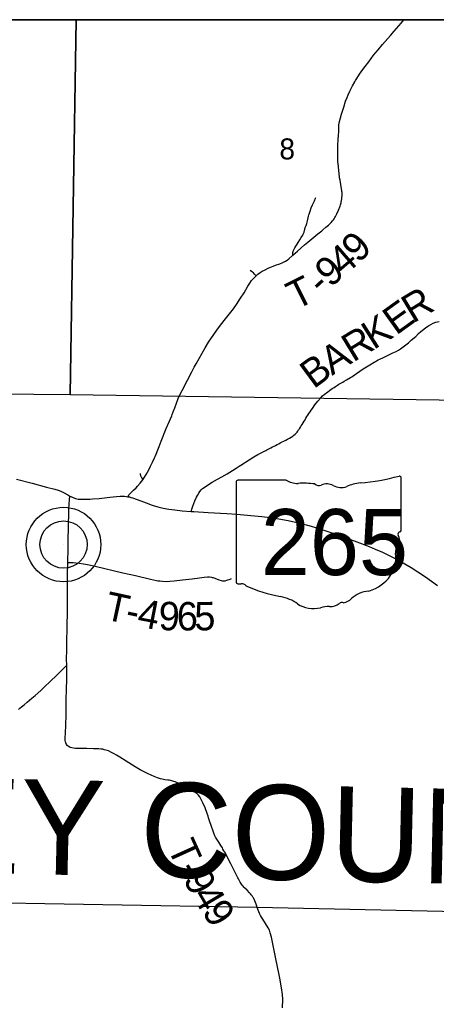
# Model space of a CAD drawing. Extents: x 0 to 34, y 0 to 22.
# Drawn here: x 5.085 to 5.917, y 18.929 to 20.9 of the extents above; entities that cross this region are included whole.
import ezdxf

# ---------------------------------------------------------------- set-up
doc = ezdxf.new("R2010")
doc.units = 0
for name, color, linetype in [('GM_X_Corporation', 7, 'Continuous'), ('GM_X_County_Text', 7, 'Continuous'), ('GM_X_Section_Text', 7, 'Continuous'), ('GM_X_State_Location', 7, 'Continuous'), ('GM_X_State_Route', 7, 'Continuous'), ('GM_X_State_Shield', 7, 'Continuous'), ('GM_X_Township_Road', 7, 'Continuous'), ('GM_X_Township_Road_Text', 7, 'Continuous'), ('GM_X_Township_Text', 7, 'Continuous'), ('GM_X_Unincorporated', 7, 'Continuous'), ('GM_X_Unincorporated_Location', 7, 'Continuous'), ('SH_Data', 7, 'Continuous')]:
    doc.layers.add(name, color=color, linetype=linetype)

msp = doc.modelspace()

# ---------------------------------------------------------------- linework, layer by layer
at = {"layer": 'GM_X_Corporation'}
for points in [[(5.1978, 20.9), (4.1826, 20.9), (4.1713, 20.1609), (5.1859, 20.1511)], [(6.2111, 20.9), (5.1978, 20.9), (5.1859, 20.1511), (6.1991, 20.1367)]]:
    msp.add_lwpolyline(points, close=True, dxfattribs=at)
at = {"layer": 'GM_X_State_Route'}
for points in [[(5.0782, 19.9821), (5.1096, 19.9743), (5.1384, 19.9666), (5.1547, 19.9622), (5.1618, 19.96), (5.1671, 19.958), (5.1722, 19.9555), (5.1809, 19.9507), (5.1851, 19.9485)], [(5.1851, 19.9485), (5.1869, 19.9475), (5.1914, 19.9456), (5.1966, 19.9438), (5.2019, 19.9426), (5.208, 19.942), (5.216, 19.942), (5.2184, 19.9421), (5.2252, 19.9424), (5.2302, 19.9427), (5.2437, 19.9439), (5.2647, 19.9461), (5.2783, 19.9478), (5.2858, 19.9484), (5.2908, 19.9485), (5.2945, 19.9482), (5.3011, 19.9472)], [(5.3011, 19.9472), (5.3039, 19.9467), (5.3068, 19.9459), (5.31, 19.9448), (5.327, 19.9387), (5.3375, 19.9348), (5.3492, 19.9306), (5.3605, 19.9272), (5.3714, 19.9245), (5.3825, 19.9224), (5.3948, 19.9208), (5.4097, 19.9193), (5.4271, 19.918), (5.4326, 19.9176), (5.4612, 19.9158), (5.499, 19.9137), (5.5182, 19.9124), (5.5683, 19.9078), (5.5855, 19.9057), (5.6027, 19.9031), (5.621, 19.8997), (5.6362, 19.8965), (5.647, 19.8939), (5.6626, 19.8897), (5.6804, 19.8843), (5.7005, 19.8778), (5.7204, 19.8709), (5.7583, 19.8571), (5.7833, 19.8476), (5.7954, 19.8427), (5.8095, 19.8363), (5.8245, 19.829), (5.8428, 19.8196), (5.8542, 19.8134), (5.8669, 19.8057), (5.8805, 19.797), (5.8954, 19.7869), (5.9197, 19.7697)]]:
    msp.add_lwpolyline(points, dxfattribs=at)
at = {"layer": 'GM_X_State_Shield'}
for p, q in [((5.847, 19.8804), (5.847, 19.9851)), ((5.5174, 19.9767), (5.5174, 19.7766)), ((5.6172, 19.9801), (5.5207, 19.9801)), ((5.847, 19.8804), (5.847, 19.8804))]:
    msp.add_line(p, q, dxfattribs=at)
for centre, major_axis, start_param, end_param in [((5.7296, 20.253), (0.3495, 0), 4.814394, 5.042369), ((5.8433, 19.9855), (0.00367, 0), 6.141152, 7.989035), ((5.5212, 19.9771), (0.00382, 0), 1.712693, 3.28349), ((5.6402, 20.0034), (0.037, 0), 4.042523, 4.731795), ((5.6524, 19.8678), (0.133, 0), 1.404758, 1.657858), ((5.6826, 19.9782), (0.0107, 0), 3.836095, 5.185415), ((5.6983, 19.955), (0.0222, 0), 0.950623, 2.079405), ((5.727, 19.9868), (0.0267, 0), 4.081561, 5.145723), ((5.7742, 19.919), (0.0703, 0), 1.699011, 2.107814), ((5.8462, 19.8727), (0.00568, 0), 1.883978, 3.671073), ((5.81, 19.8595), (0.0341, 0), 5.934695, 6.695948), ((5.8431, 19.88), (0.00393, 0), 5.05454, 6.418171), ((5.8601, 19.8366), (0.0248, 0), 2.387724, 3.262537), ((5.7492, 19.8233), (0.0874, 0), 5.101752, 6.440018), ((5.5212, 19.7761), (0.00385, 0), 3.00124, 4.508301), ((5.5218, 19.7966), (0.0294, 0), 4.665946, 4.897461), ((5.5278, 19.765), (0.0106, 0), 0.519207, 1.627899), ((5.6616, 19.9448), (0.2524, 0), 4.195997, 4.488961), ((5.5864, 19.6867), (0.079, 0), 0.823519, 1.323587), ((5.786, 19.7204), (0.0479, 0), 1.647645, 2.488434), ((5.6718, 19.764), (0.0501, 0), 4.026481, 4.996735), ((5.7008, 19.6948), (0.0412, 0), 1.495662, 1.94098), ((5.7044, 19.749), (0.0267, 0), 4.691044, 5.507374), ((5.7286, 19.7297), (0.00752, 0), 1.147584, 2.315152), ((5.7254, 19.7572), (0.0282, 0), 4.937069, 5.64225)]:
    msp.add_ellipse(centre, major_axis=major_axis, ratio=0.8, start_param=start_param, end_param=end_param, dxfattribs=at)
at = {"layer": 'GM_X_Township_Road'}
for points in [[(5.6308, 20.4295), (5.6352, 20.4335), (5.6399, 20.4376), (5.6541, 20.4505), (5.6603, 20.4557), (5.6806, 20.472), (5.6882, 20.4783), (5.6906, 20.4803), (5.6967, 20.4854), (5.7019, 20.4899), (5.7073, 20.495), (5.7101, 20.4983), (5.7117, 20.5004), (5.713, 20.5023), (5.7144, 20.5046), (5.7158, 20.5071), (5.7182, 20.5122), (5.7215, 20.5195), (5.725, 20.5275), (5.7258, 20.53), (5.7265, 20.5322), (5.727, 20.5339), (5.7274, 20.5358), (5.7279, 20.5386), (5.7284, 20.5419), (5.7287, 20.5449), (5.7289, 20.5481), (5.7289, 20.5527), (5.7289, 20.5551), (5.7288, 20.557), (5.7286, 20.5586), (5.728, 20.5623), (5.7263, 20.5711), (5.7249, 20.5795), (5.7241, 20.5842), (5.723, 20.594), (5.7227, 20.5972), (5.7215, 20.6077), (5.7207, 20.617), (5.7202, 20.6263), (5.7202, 20.6449), (5.7204, 20.6517), (5.721, 20.6581), (5.7214, 20.6622), (5.7218, 20.6678), (5.7223, 20.6771), (5.7224, 20.6845), (5.7228, 20.6901), (5.7232, 20.6932), (5.724, 20.6968), (5.7259, 20.704), (5.7279, 20.7112), (5.7322, 20.7255), (5.7361, 20.7372), (5.7389, 20.7448), (5.741, 20.75), (5.7443, 20.7573), (5.7497, 20.7678), (5.7543, 20.7759), (5.7559, 20.7786), (5.7585, 20.7828), (5.7639, 20.7911), (5.7707, 20.8007), (5.7751, 20.8067), (5.7821, 20.8161), (5.7919, 20.8289), (5.8008, 20.8401), (5.8095, 20.8506), (5.8149, 20.8566), (5.8259, 20.8683), (5.8332, 20.8768), (5.8467, 20.893), (5.8523, 20.9)], [(5.6308, 20.4295), (5.6305, 20.4313), (5.6304, 20.4322), (5.6304, 20.4329), (5.6304, 20.4337), (5.6305, 20.4346), (5.6306, 20.4355), (5.6309, 20.4364), (5.6312, 20.4373), (5.6315, 20.438), (5.6327, 20.4405), (5.6347, 20.4441), (5.6368, 20.4477), (5.6394, 20.4519), (5.6413, 20.455), (5.6445, 20.4604), (5.6469, 20.4647), (5.6503, 20.4699), (5.6512, 20.4715), (5.6521, 20.4731), (5.6525, 20.4742), (5.6529, 20.4754), (5.6533, 20.4769), (5.6537, 20.4784), (5.6544, 20.4815), (5.6548, 20.4829), (5.6554, 20.4846), (5.656, 20.486), (5.6573, 20.4888), (5.6582, 20.4908), (5.6588, 20.4928), (5.6601, 20.4982), (5.6612, 20.5043), (5.6619, 20.5078), (5.6625, 20.5102), (5.663, 20.5116), (5.6649, 20.5179), (5.6672, 20.5243), (5.6696, 20.53), (5.6737, 20.5383), (5.6759, 20.5437), (5.6763, 20.5447)], [(5.5573, 20.3885), (5.5609, 20.3916), (5.5653, 20.395), (5.5696, 20.3976), (5.574, 20.3998), (5.5829, 20.4042), (5.5881, 20.4064), (5.591, 20.4075), (5.5956, 20.4094), (5.6043, 20.4126), (5.6106, 20.415), (5.6157, 20.4174), (5.6194, 20.4196), (5.6229, 20.4222), (5.6308, 20.4295)], [(5.5573, 20.3885), (5.554, 20.3919), (5.5519, 20.3941), (5.548, 20.3973), (5.5455, 20.3991)], [(5.3309, 19.981), (5.3343, 19.986), (5.3375, 19.9913), (5.3428, 20.0012), (5.3464, 20.0084), (5.3503, 20.0162), (5.3543, 20.0246), (5.3555, 20.0274), (5.3574, 20.032), (5.3608, 20.0407), (5.3634, 20.0477), (5.3674, 20.0581), (5.3775, 20.0834), (5.3832, 20.0966), (5.3885, 20.1091), (5.3895, 20.1114), (5.3916, 20.1166), (5.3947, 20.1247), (5.4017, 20.1433), (5.4048, 20.1508), (5.4092, 20.1597), (5.4201, 20.1799), (5.429, 20.1969), (5.4337, 20.2057), (5.4377, 20.2127), (5.4437, 20.2236), (5.4554, 20.2448), (5.4622, 20.2559), (5.4726, 20.2714), (5.4786, 20.2801), (5.4859, 20.2901), (5.4959, 20.3027), (5.5117, 20.3227), (5.518, 20.3312), (5.5263, 20.3436), (5.5331, 20.3547), (5.5408, 20.3675), (5.5447, 20.3738), (5.5483, 20.3788), (5.5523, 20.3836), (5.5557, 20.3872), (5.5573, 20.3885)], [(5.4271, 19.918), (5.4294, 19.9246), (5.4305, 19.9281), (5.4348, 19.939), (5.4382, 19.9464), (5.4399, 19.9497), (5.4427, 19.9545), (5.4448, 19.9576), (5.4476, 19.9609), (5.4503, 19.9635), (5.4532, 19.9658), (5.4599, 19.9703), (5.4694, 19.9761), (5.4797, 19.982), (5.4889, 19.9871), (5.4991, 19.9931), (5.5102, 19.9998), (5.5176, 20.0044), (5.5234, 20.0081), (5.5265, 20.0101), (5.5436, 20.0212), (5.5524, 20.0267), (5.5609, 20.0316), (5.563, 20.0327), (5.5711, 20.0369), (5.5721, 20.0375), (5.5737, 20.0383), (5.5763, 20.0396), (5.5784, 20.0407), (5.5815, 20.0424), (5.5842, 20.0437), (5.5868, 20.0451), (5.59, 20.0467), (5.5932, 20.0484), (5.5959, 20.0498), (5.5991, 20.0514), (5.6023, 20.0531), (5.6055, 20.0548), (5.6093, 20.0567), (5.6125, 20.0585), (5.6164, 20.0603), (5.6197, 20.0621), (5.6241, 20.0643), (5.6273, 20.0663), (5.6304, 20.0684), (5.6328, 20.0702), (5.6352, 20.0722), (5.6378, 20.0748), (5.639, 20.0762), (5.6405, 20.0782), (5.6422, 20.0807), (5.6436, 20.0827), (5.6456, 20.0859), (5.6472, 20.0885), (5.6491, 20.0916), (5.651, 20.0948), (5.6529, 20.0979), (5.6549, 20.101), (5.6568, 20.1042), (5.6588, 20.1073), (5.6608, 20.1104), (5.6628, 20.1135), (5.6652, 20.1171), (5.6673, 20.1201), (5.6697, 20.1237), (5.6747, 20.1308), (5.6805, 20.1381), (5.6862, 20.1447), (5.69, 20.1487), (5.6932, 20.1516), (5.7002, 20.1568), (5.7037, 20.1593), (5.7062, 20.1611), (5.7093, 20.1632), (5.7129, 20.1656), (5.7155, 20.1673), (5.7197, 20.1699), (5.7228, 20.1719), (5.7276, 20.1747), (5.7303, 20.1763), (5.733, 20.1778), (5.7378, 20.1805), (5.7458, 20.1853), (5.7483, 20.187), (5.7514, 20.189), (5.7714, 20.2025), (5.7745, 20.2046), (5.7844, 20.2109), (5.7929, 20.216), (5.7956, 20.2175), (5.7977, 20.2186), (5.801, 20.2204), (5.8046, 20.2221), (5.8114, 20.2255), (5.8187, 20.2289), (5.8306, 20.2343), (5.837, 20.2374), (5.8418, 20.2401), (5.8459, 20.2428), (5.8513, 20.2469), (5.8562, 20.2507), (5.8616, 20.2549), (5.8673, 20.2597), (5.8761, 20.2674), (5.8819, 20.273), (5.8864, 20.2771), (5.8892, 20.2795), (5.8931, 20.2825), (5.8986, 20.2865), (5.9017, 20.2886), (5.9065, 20.2915), (5.911, 20.2936), (5.9162, 20.2956), (5.9228, 20.2972)], [(5.3253, 19.9935), (5.3256, 19.9914), (5.3259, 19.9903), (5.3261, 19.9895), (5.3264, 19.9888), (5.3268, 19.9881), (5.3274, 19.9867), (5.329, 19.9841), (5.3309, 19.981)], [(5.3011, 19.9472), (5.3038, 19.9516), (5.3056, 19.9539), (5.3079, 19.9562), (5.3123, 19.9603), (5.3172, 19.965), (5.3202, 19.9681), (5.3255, 19.9741), (5.3309, 19.981)], [(5.1808, 19.8157), (5.1814, 19.8436), (5.1819, 19.8641), (5.1823, 19.8821), (5.1825, 19.8951), (5.1828, 19.9088), (5.1832, 19.9218), (5.1837, 19.933), (5.1844, 19.941), (5.1851, 19.9485)], [(5.1851, 19.9485), (5.1869, 19.9475), (5.1914, 19.9456), (5.1966, 19.9438), (5.2019, 19.9426), (5.208, 19.942), (5.216, 19.942), (5.2184, 19.9421), (5.2252, 19.9424), (5.2302, 19.9427), (5.2437, 19.9439), (5.2647, 19.9461), (5.2783, 19.9478), (5.2858, 19.9484), (5.2908, 19.9485), (5.2945, 19.9482), (5.3011, 19.9472)], [(5.1787, 19.6108), (5.1785, 19.6226), (5.1788, 19.6413), (5.1789, 19.6518), (5.1793, 19.6642), (5.1796, 19.6785), (5.1796, 19.6841), (5.1799, 19.6984), (5.18, 19.7071), (5.1801, 19.7151), (5.1801, 19.7201), (5.1803, 19.7292), (5.1803, 19.7323), (5.1803, 19.736), (5.1803, 19.7456), (5.1804, 19.7518), (5.1801, 19.7617), (5.1804, 19.7704), (5.1805, 19.7797), (5.1804, 19.7909), (5.1804, 19.7964), (5.1807, 19.8107), (5.1808, 19.8157)], [(5.1808, 19.8157), (5.1861, 19.8156), (5.1917, 19.8155), (5.1972, 19.8153), (5.2034, 19.8147), (5.2126, 19.8132), (5.2205, 19.8116), (5.2357, 19.8084), (5.2908, 19.7954), (5.3163, 19.7897), (5.3459, 19.7827), (5.3521, 19.7813), (5.358, 19.7801), (5.3611, 19.7795), (5.3647, 19.7789), (5.3704, 19.7784), (5.3772, 19.7781), (5.3846, 19.7783), (5.3933, 19.7789), (5.41, 19.7809), (5.4291, 19.7835), (5.4438, 19.7855), (5.4537, 19.7867), (5.4598, 19.787), (5.4642, 19.7869), (5.4679, 19.7864), (5.4697, 19.7861), (5.4715, 19.7856), (5.475, 19.7843), (5.483, 19.781), (5.4872, 19.7798), (5.4897, 19.7793), (5.4927, 19.7792), (5.4952, 19.7795), (5.4988, 19.7804), (5.5053, 19.7826), (5.5081, 19.7839)], [(5.0824, 19.5223), (5.0852, 19.5247), (5.0885, 19.5275), (5.0937, 19.5318), (5.0999, 19.5369), (5.1093, 19.5448), (5.1158, 19.5505), (5.1267, 19.5604), (5.1371, 19.57), (5.143, 19.5753), (5.1492, 19.5812), (5.1559, 19.5876), (5.1642, 19.5959), (5.1698, 19.6017), (5.1741, 19.6061), (5.1787, 19.6108)], [(5.5593, 19.127), (5.5581, 19.1314), (5.5573, 19.1336), (5.5561, 19.1369), (5.5548, 19.1399), (5.5527, 19.1444), (5.5517, 19.146), (5.5508, 19.1476), (5.5492, 19.1498), (5.5475, 19.1521), (5.5459, 19.1539), (5.5442, 19.1558), (5.539, 19.1612), (5.5342, 19.166), (5.5328, 19.1675), (5.5311, 19.1693), (5.5293, 19.1714), (5.5269, 19.175), (5.5253, 19.1776), (5.5217, 19.1841), (5.5206, 19.1863), (5.5195, 19.1884), (5.5159, 19.1955), (5.5066, 19.2138), (5.4987, 19.2292), (5.4964, 19.2336), (5.4945, 19.2373), (5.493, 19.2399), (5.491, 19.2435), (5.4898, 19.2456), (5.4867, 19.2507), (5.4824, 19.2571), (5.4785, 19.263), (5.4762, 19.2673), (5.4748, 19.27), (5.4726, 19.2749), (5.4665, 19.2922), (5.4652, 19.2961), (5.4622, 19.306), (5.4612, 19.3089), (5.4595, 19.3142), (5.4551, 19.3258), (5.4507, 19.336), (5.4467, 19.3437), (5.4445, 19.3475), (5.4419, 19.351), (5.441, 19.3521), (5.4398, 19.3532), (5.4386, 19.3542), (5.4374, 19.3552), (5.4354, 19.3566), (5.4332, 19.358), (5.4213, 19.3645), (5.4109, 19.3702), (5.4004, 19.3755), (5.3952, 19.3777), (5.3926, 19.3786), (5.3905, 19.3793), (5.3884, 19.3799), (5.3863, 19.3803), (5.3834, 19.3809), (5.3808, 19.3813), (5.3747, 19.3819), (5.3692, 19.3829), (5.3662, 19.3836), (5.3602, 19.3855), (5.3533, 19.3882), (5.3414, 19.3935), (5.3319, 19.3982), (5.3254, 19.4017), (5.3157, 19.4074), (5.2974, 19.419), (5.2848, 19.427), (5.2785, 19.4309), (5.2736, 19.4338), (5.267, 19.4372), (5.2619, 19.4394), (5.2572, 19.441), (5.2538, 19.4419), (5.2506, 19.4427), (5.2469, 19.4432), (5.2426, 19.4435), (5.2321, 19.4438), (5.219, 19.444), (5.2041, 19.4442), (5.1992, 19.4444), (5.1961, 19.4445), (5.1923, 19.4448), (5.1887, 19.4455), (5.1857, 19.4464), (5.1834, 19.4474), (5.1814, 19.4488), (5.1797, 19.4505), (5.1783, 19.4525), (5.177, 19.4553), (5.1762, 19.4577), (5.1758, 19.4601), (5.1757, 19.462), (5.1757, 19.4638), (5.1757, 19.4669), (5.1761, 19.4737), (5.1762, 19.4774), (5.1765, 19.4805), (5.1768, 19.4855), (5.1771, 19.4923), (5.1776, 19.5097), (5.1778, 19.5246), (5.1779, 19.5413), (5.1782, 19.5625), (5.179, 19.5823), (5.1793, 19.596), (5.1791, 19.6034), (5.1787, 19.6108)], [(5.6097, 18.9261), (5.6105, 18.9428), (5.6096, 18.9527), (5.6078, 18.9662), (5.6048, 18.9853), (5.6035, 18.992), (5.5959, 19.0273), (5.5908, 19.0539), (5.5878, 19.0678), (5.5854, 19.0764), (5.5838, 19.0814), (5.5816, 19.0864), (5.5761, 19.095), (5.5704, 19.1031), (5.5677, 19.1072), (5.5657, 19.1108), (5.5642, 19.1147), (5.5593, 19.127)]]:
    msp.add_lwpolyline(points, dxfattribs=at)
at = {"layer": 'GM_X_Township_Text'}
for points in [[(2.1, 19.1775), (2.6044, 19.174), (2.6249, 19.1744), (2.7359, 19.1727), (3.4968, 19.1598), (3.523, 19.1623), (4.1413, 19.1495), (4.1773, 19.1491), (4.6334, 19.1433), (5.5591, 19.1275), (6.3618, 19.1099), (6.6786, 19.1086), (6.7436, 19.1061), (6.828, 19.1033), (6.8907, 19.103), (7.1115, 19.0999), (7.1957, 19.0991), (7.1974, 19.2018), (7.1981, 19.2461), (7.1982, 19.2496), (7.2244, 20.2649), (7.231, 20.9)], [(7.231, 20.9), (2.1, 20.9), (2.1, 19.1775)]]:
    msp.add_lwpolyline(points, dxfattribs=at)
at = {"layer": 'GM_X_Unincorporated'}
for radius in [0.0744, 0.0472]:
    msp.add_circle((5.1724, 19.8517), radius, dxfattribs=at)
at = {"layer": 'GM_X_Unincorporated_Location'}
msp.add_line((5.1724, 19.8517), (5.1724, 19.8517), dxfattribs=at)
at = {"layer": 'SH_Data'}
msp.add_line((2.1, 20.9), (8.9, 20.9), dxfattribs=at)

# ---------------------------------------------------------------- texts
at = {"layer": 'GM_X_County_Text'}
msp.add_text('GUERNSEY COUNTY', height=0.189394, rotation=358.7038, dxfattribs=at).set_placement((3.8321, 19.2222))
at = {"layer": 'GM_X_Section_Text'}
msp.add_text('8', height=0.0419, rotation=0, dxfattribs=at).set_placement((5.6037, 20.621))
at = {"layer": 'GM_X_State_Location'}
for s in ['s', 'r']:
    msp.add_text(s, height=0.000189, dxfattribs=at).set_placement((5.6785, 19.8633))
msp.add_text('265', height=0.000189, rotation=0, dxfattribs=at).set_placement((5.6116, 19.8495))
at = {"layer": 'GM_X_State_Shield'}
msp.add_text('265', height=0.13184, dxfattribs=at).set_placement((5.5666, 19.7907))
at = {"layer": 'GM_X_Township_Road_Text'}
for s, rotation, p in [('9', 44.583, (5.7618, 20.4121)), ('4', 40.8033, (5.7323, 20.3865)), ('9', 40.6352, (5.7056, 20.3636)), ('T', 26.6225, (5.6367, 20.3195)), ('-', 42.371, (5.6887, 20.3481)), ('R', 31.1692, (5.8705, 20.2927)), ('E', 35.6995, (5.8369, 20.2686)), ('K', 32.3828, (5.7918, 20.2398)), ('R', 31.3761, (5.751, 20.2149)), ('A', 32.0733, (5.7088, 20.1885)), ('B', 36.368, (5.6721, 20.1614)), ('T', 347.8184, (5.2516, 19.7029)), ('4', 349.0381, (5.3173, 19.6888)), ('9', 358.3817, (5.3617, 19.681)), ('6', 0.3457, (5.3988, 19.68)), ('5', 0.4677, (5.4339, 19.6802)), ('-', 348.0133, (5.2934, 19.6939)), ('T', 294.3681, (5.3792, 19.2468)), ('-', 299.0461, (5.3991, 19.2036)), ('9', 298.9303, (5.4104, 19.1832)), ('4', 300.5098, (5.4281, 19.1511)), ('9', 303.6567, (5.4477, 19.118))]:
    msp.add_text(s, height=0.0568, rotation=rotation, dxfattribs=at).set_placement(p)

doc.saveas('drawing.dxf')
